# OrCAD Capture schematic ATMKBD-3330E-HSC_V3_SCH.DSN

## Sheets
1 1. TITLE: title: ATM3330e PV Keyboard Reference Design; rev: 3; note: <078-30-611-xxxx>
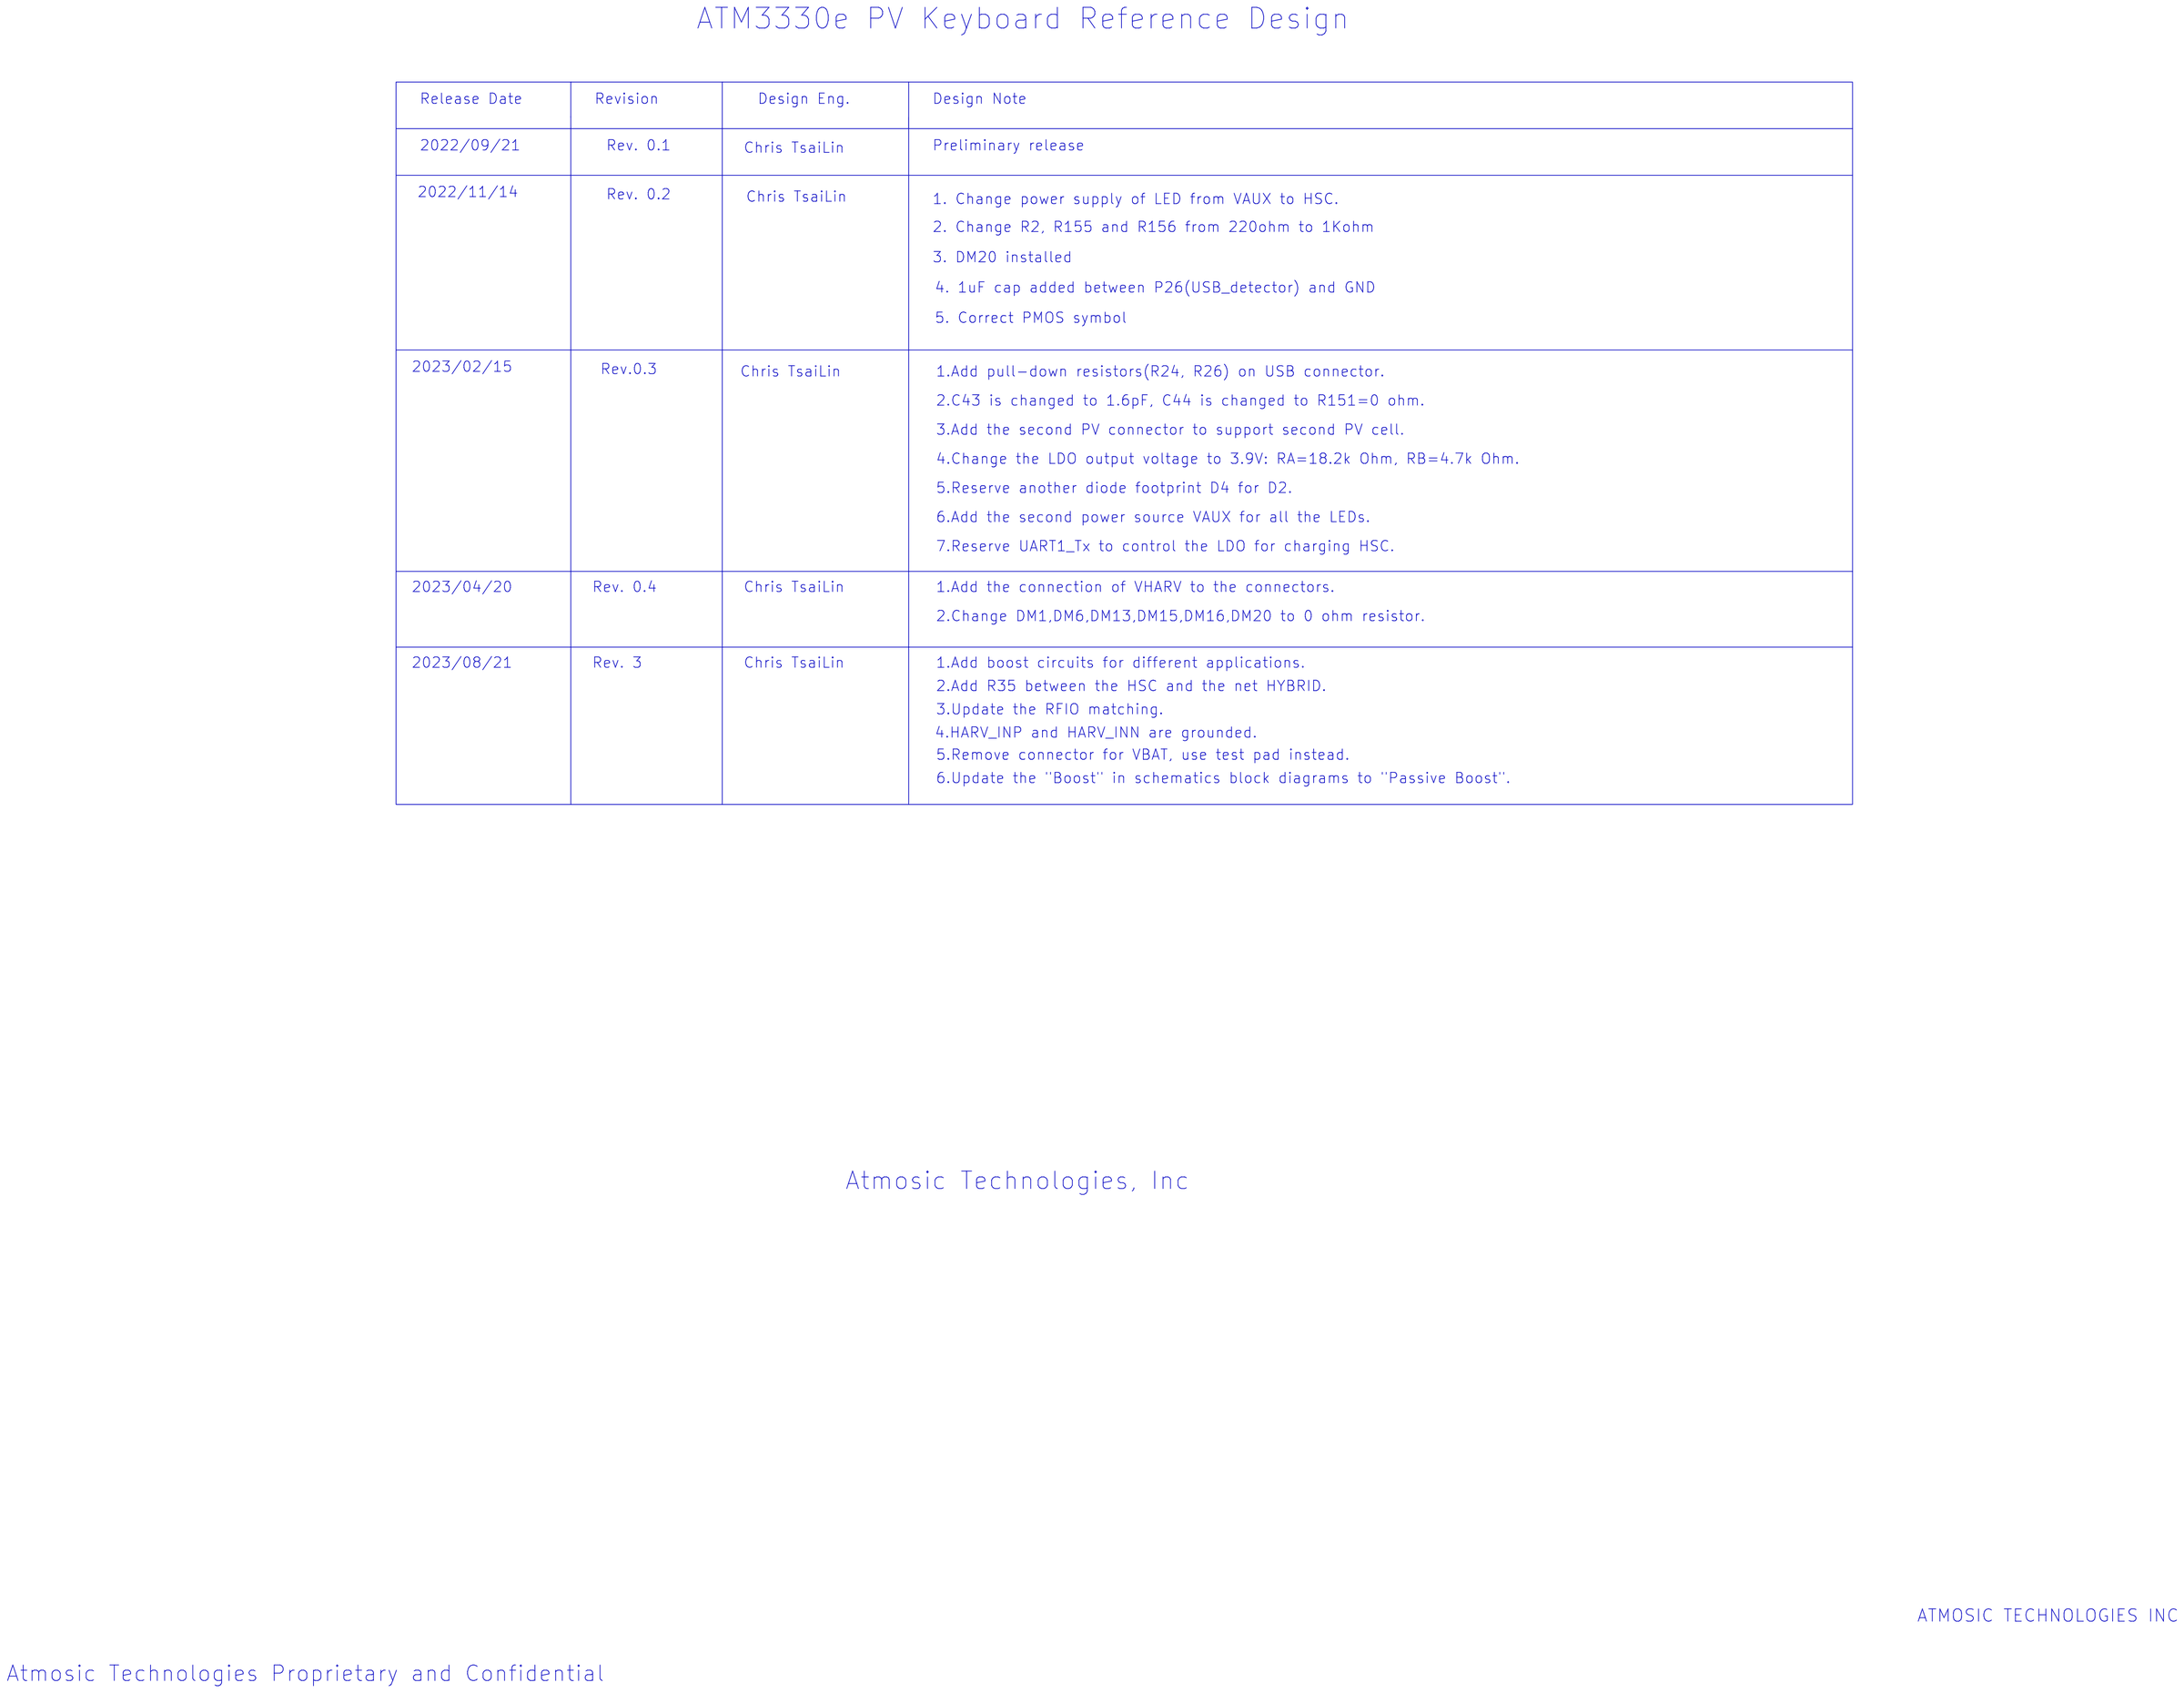
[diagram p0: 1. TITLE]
2 2. BLOCK DIAGRAM_1
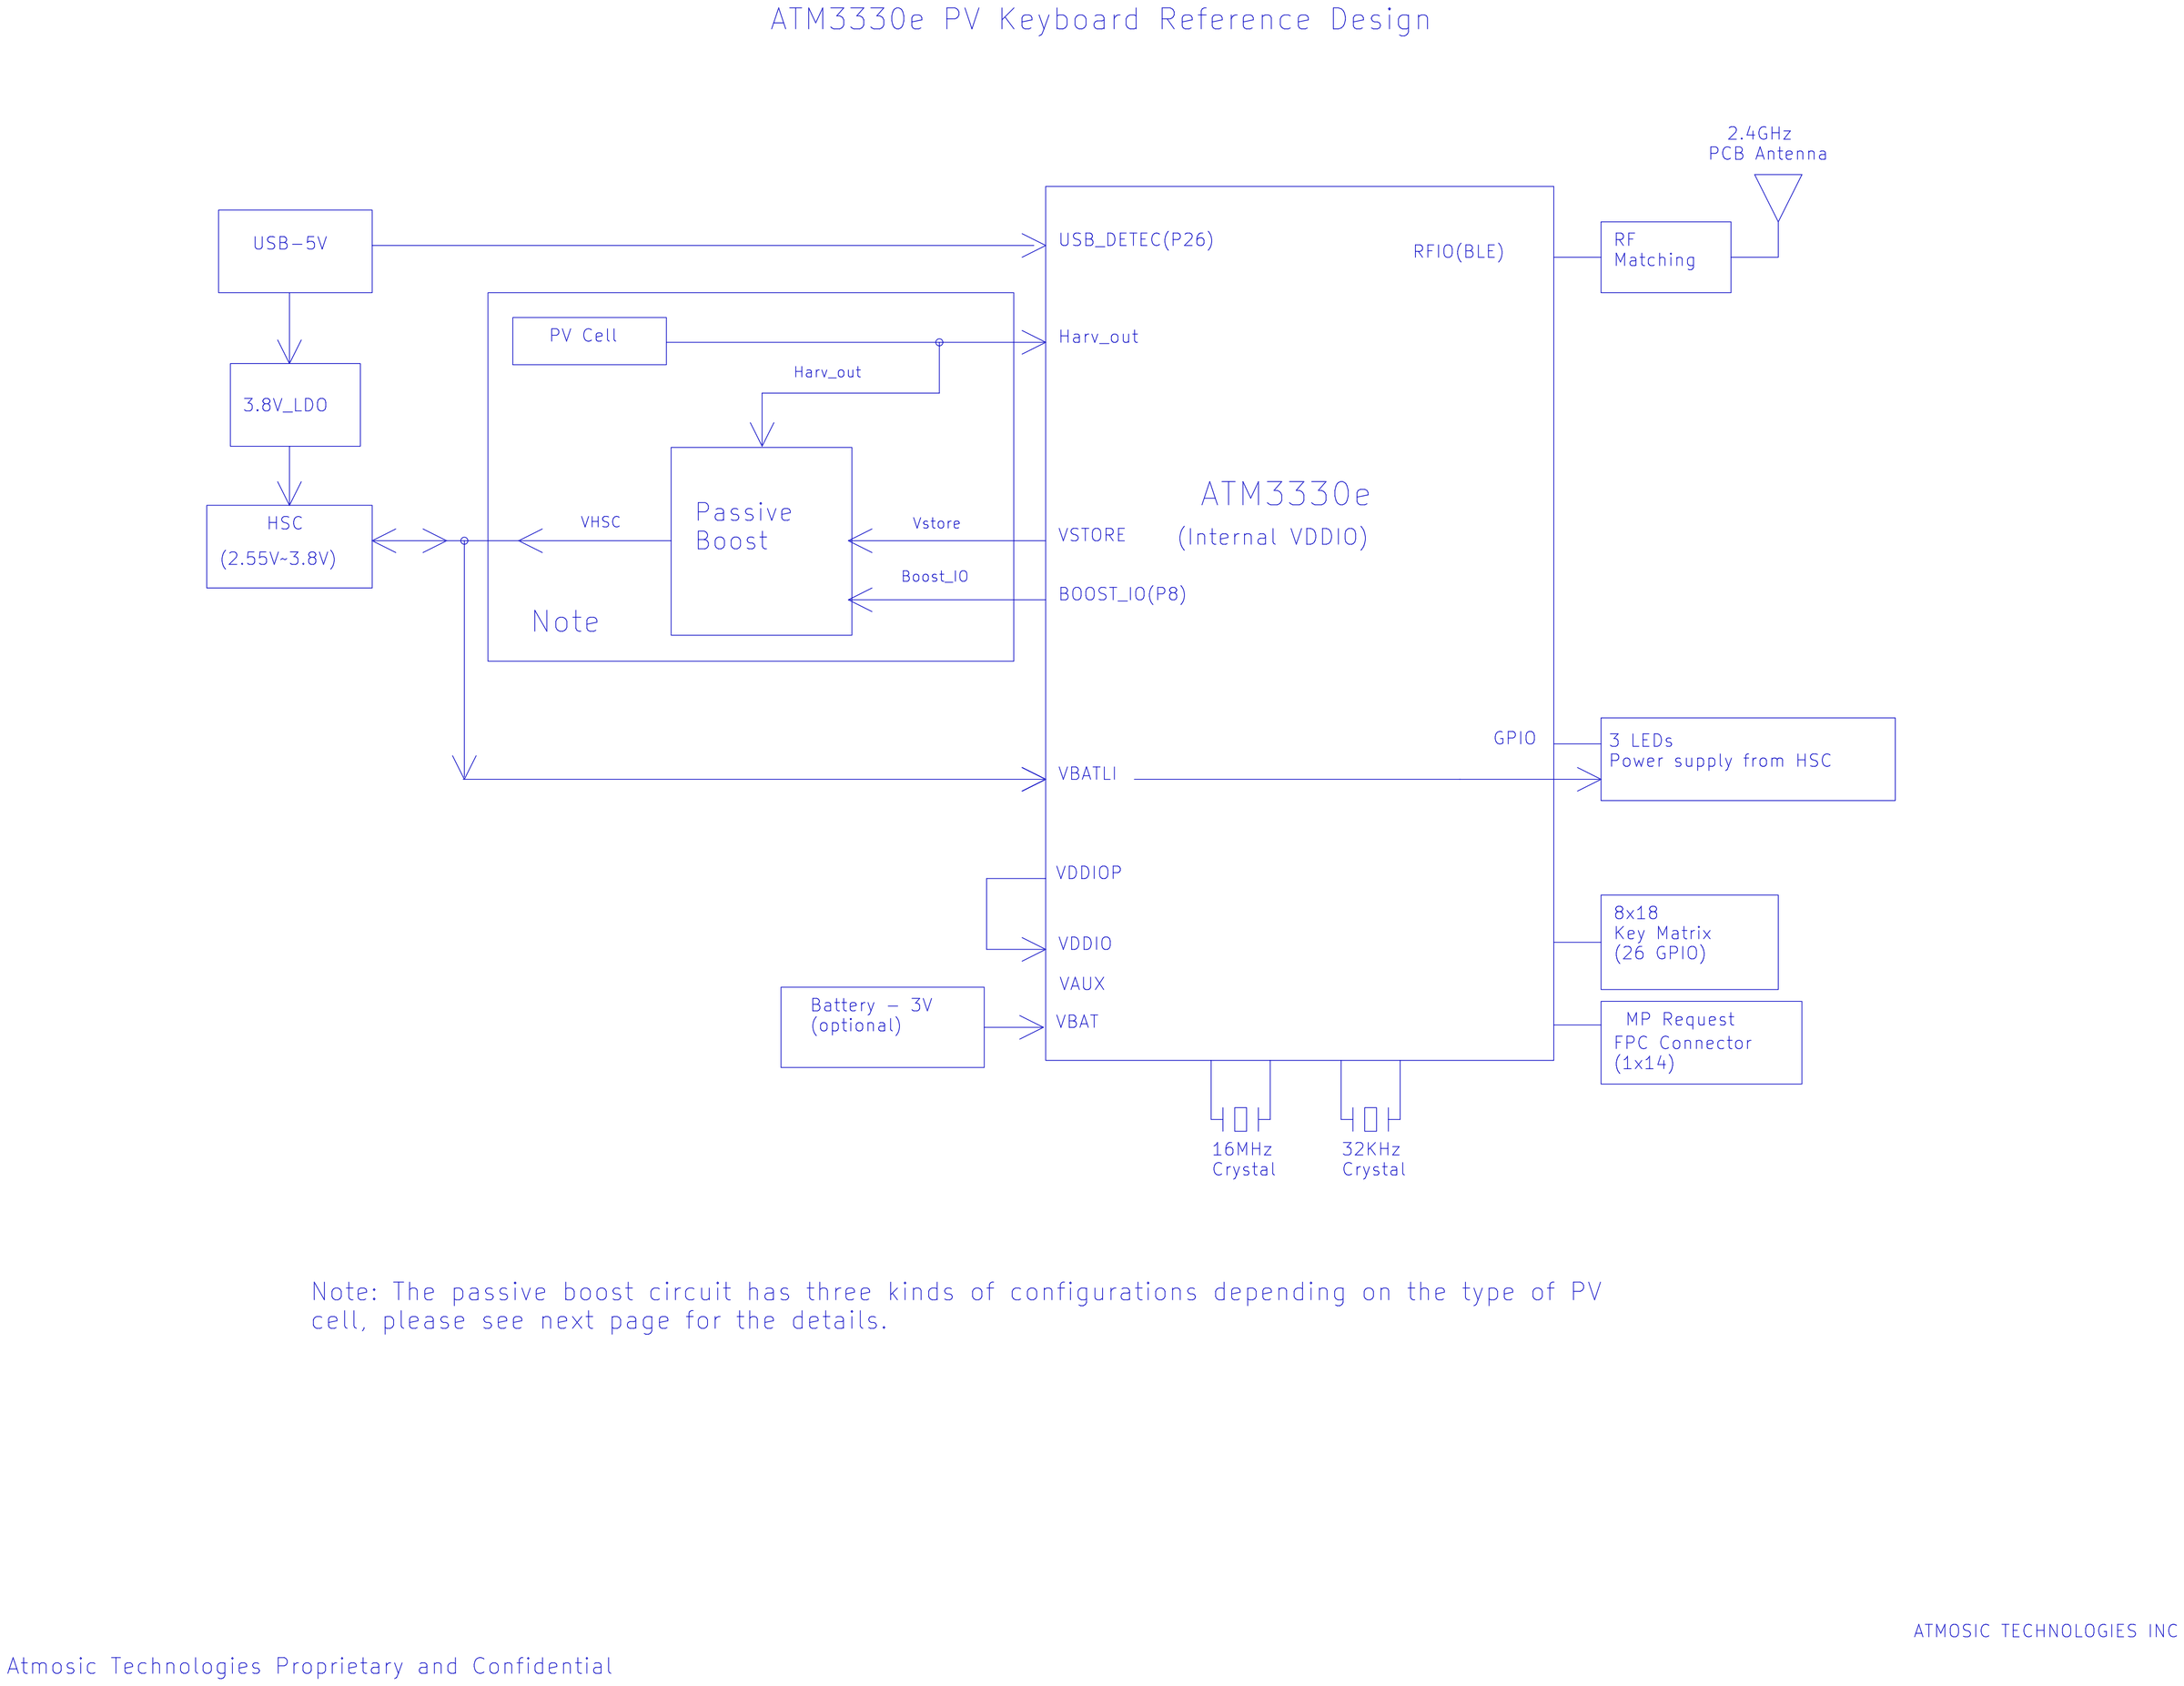
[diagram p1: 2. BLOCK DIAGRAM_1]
3 3. BLOCK DIAGRAM_2
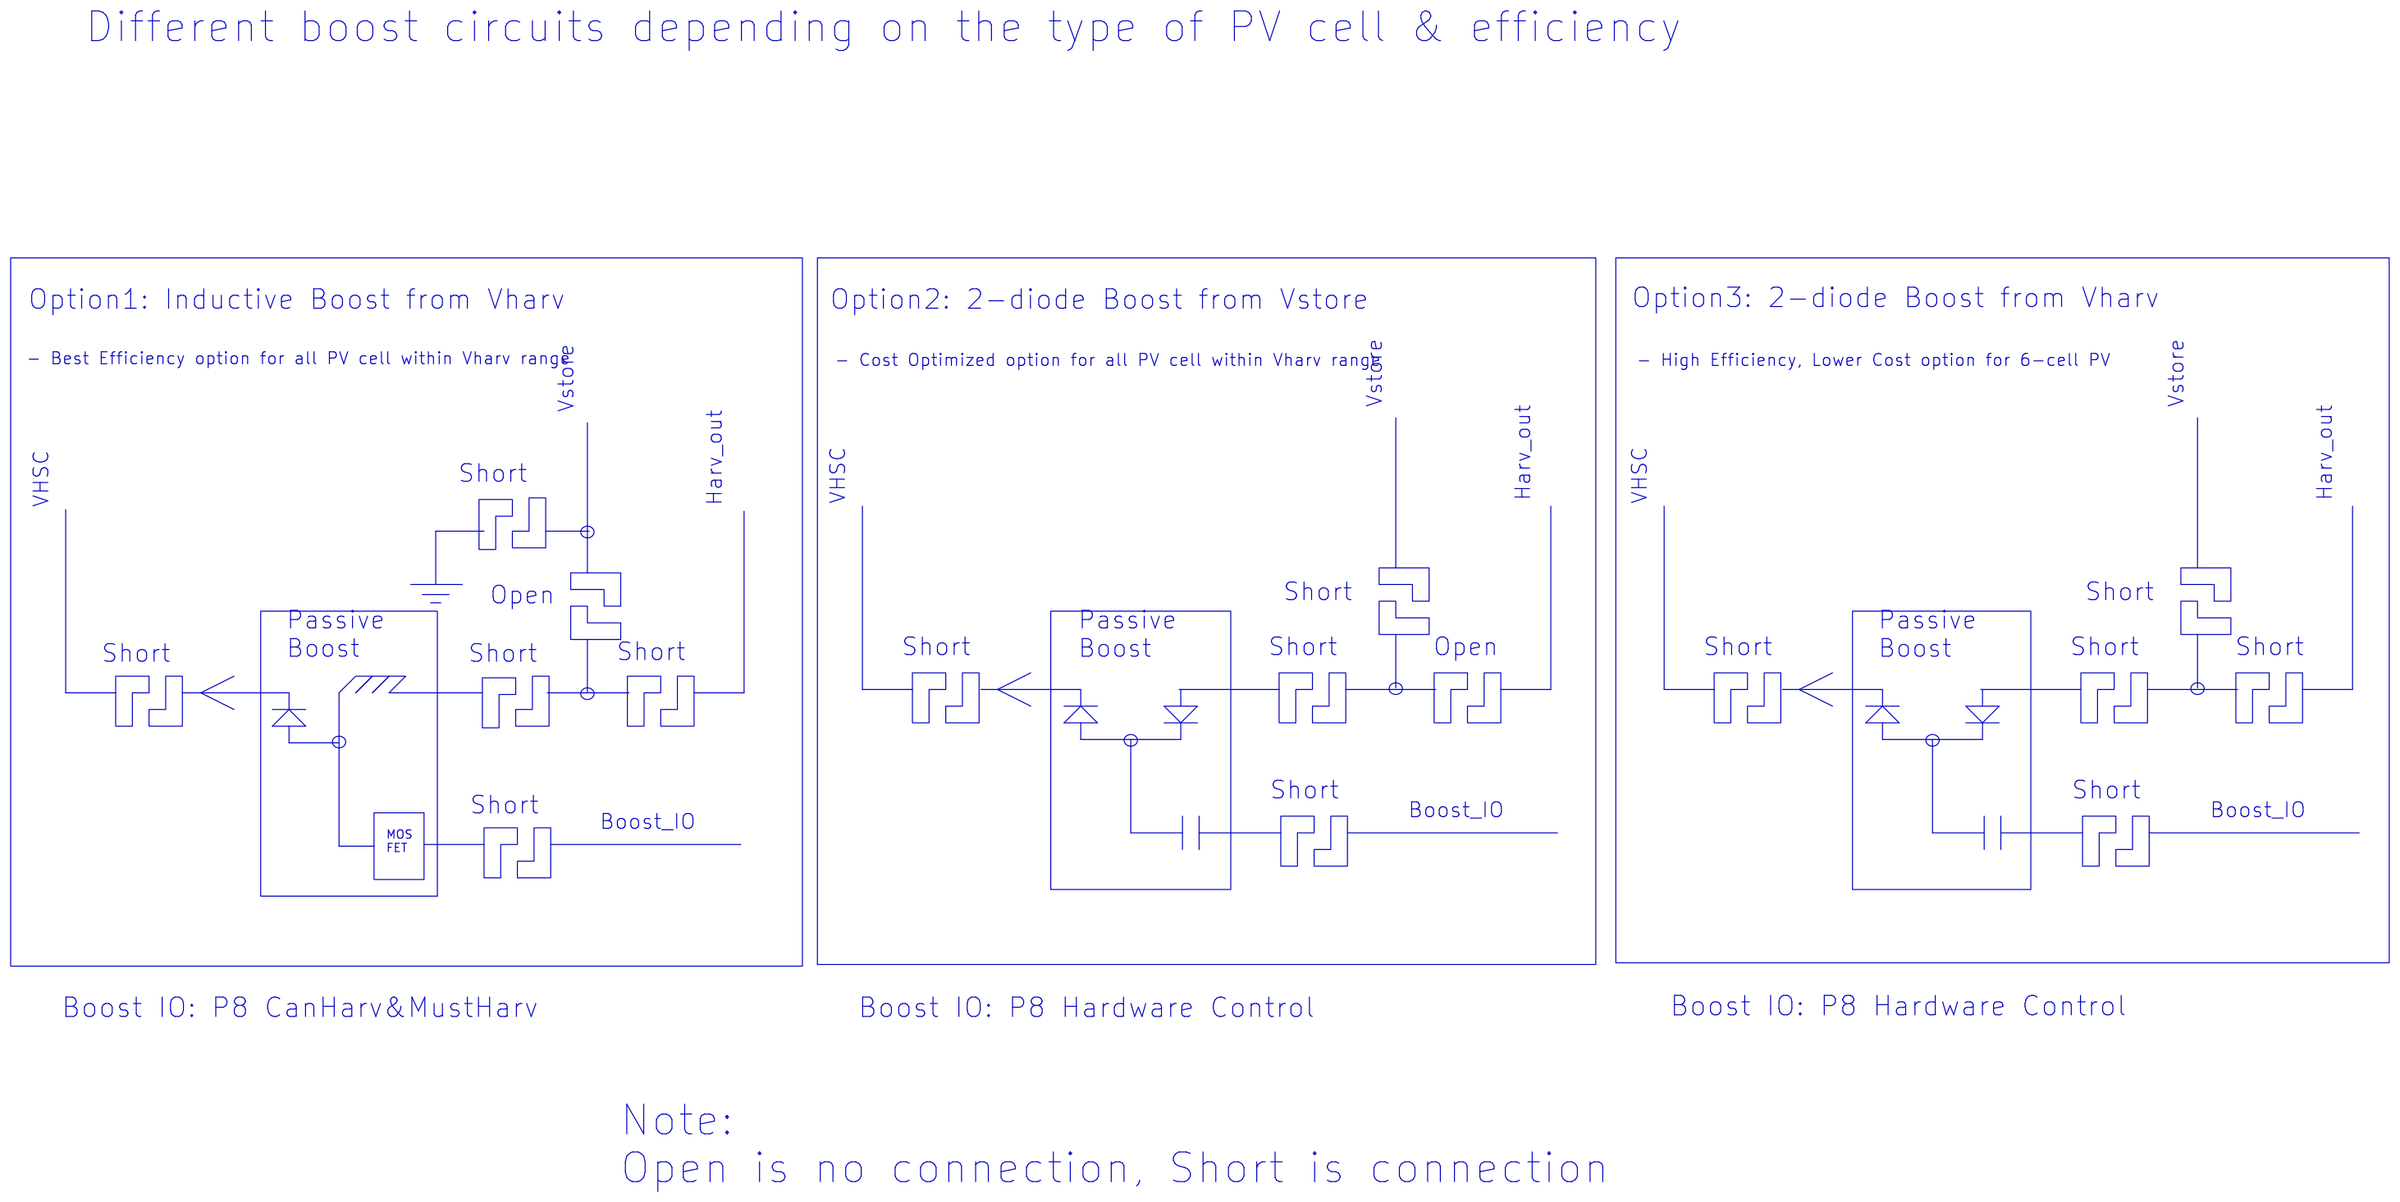
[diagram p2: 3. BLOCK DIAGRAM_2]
4 4. ATM3330e: size C
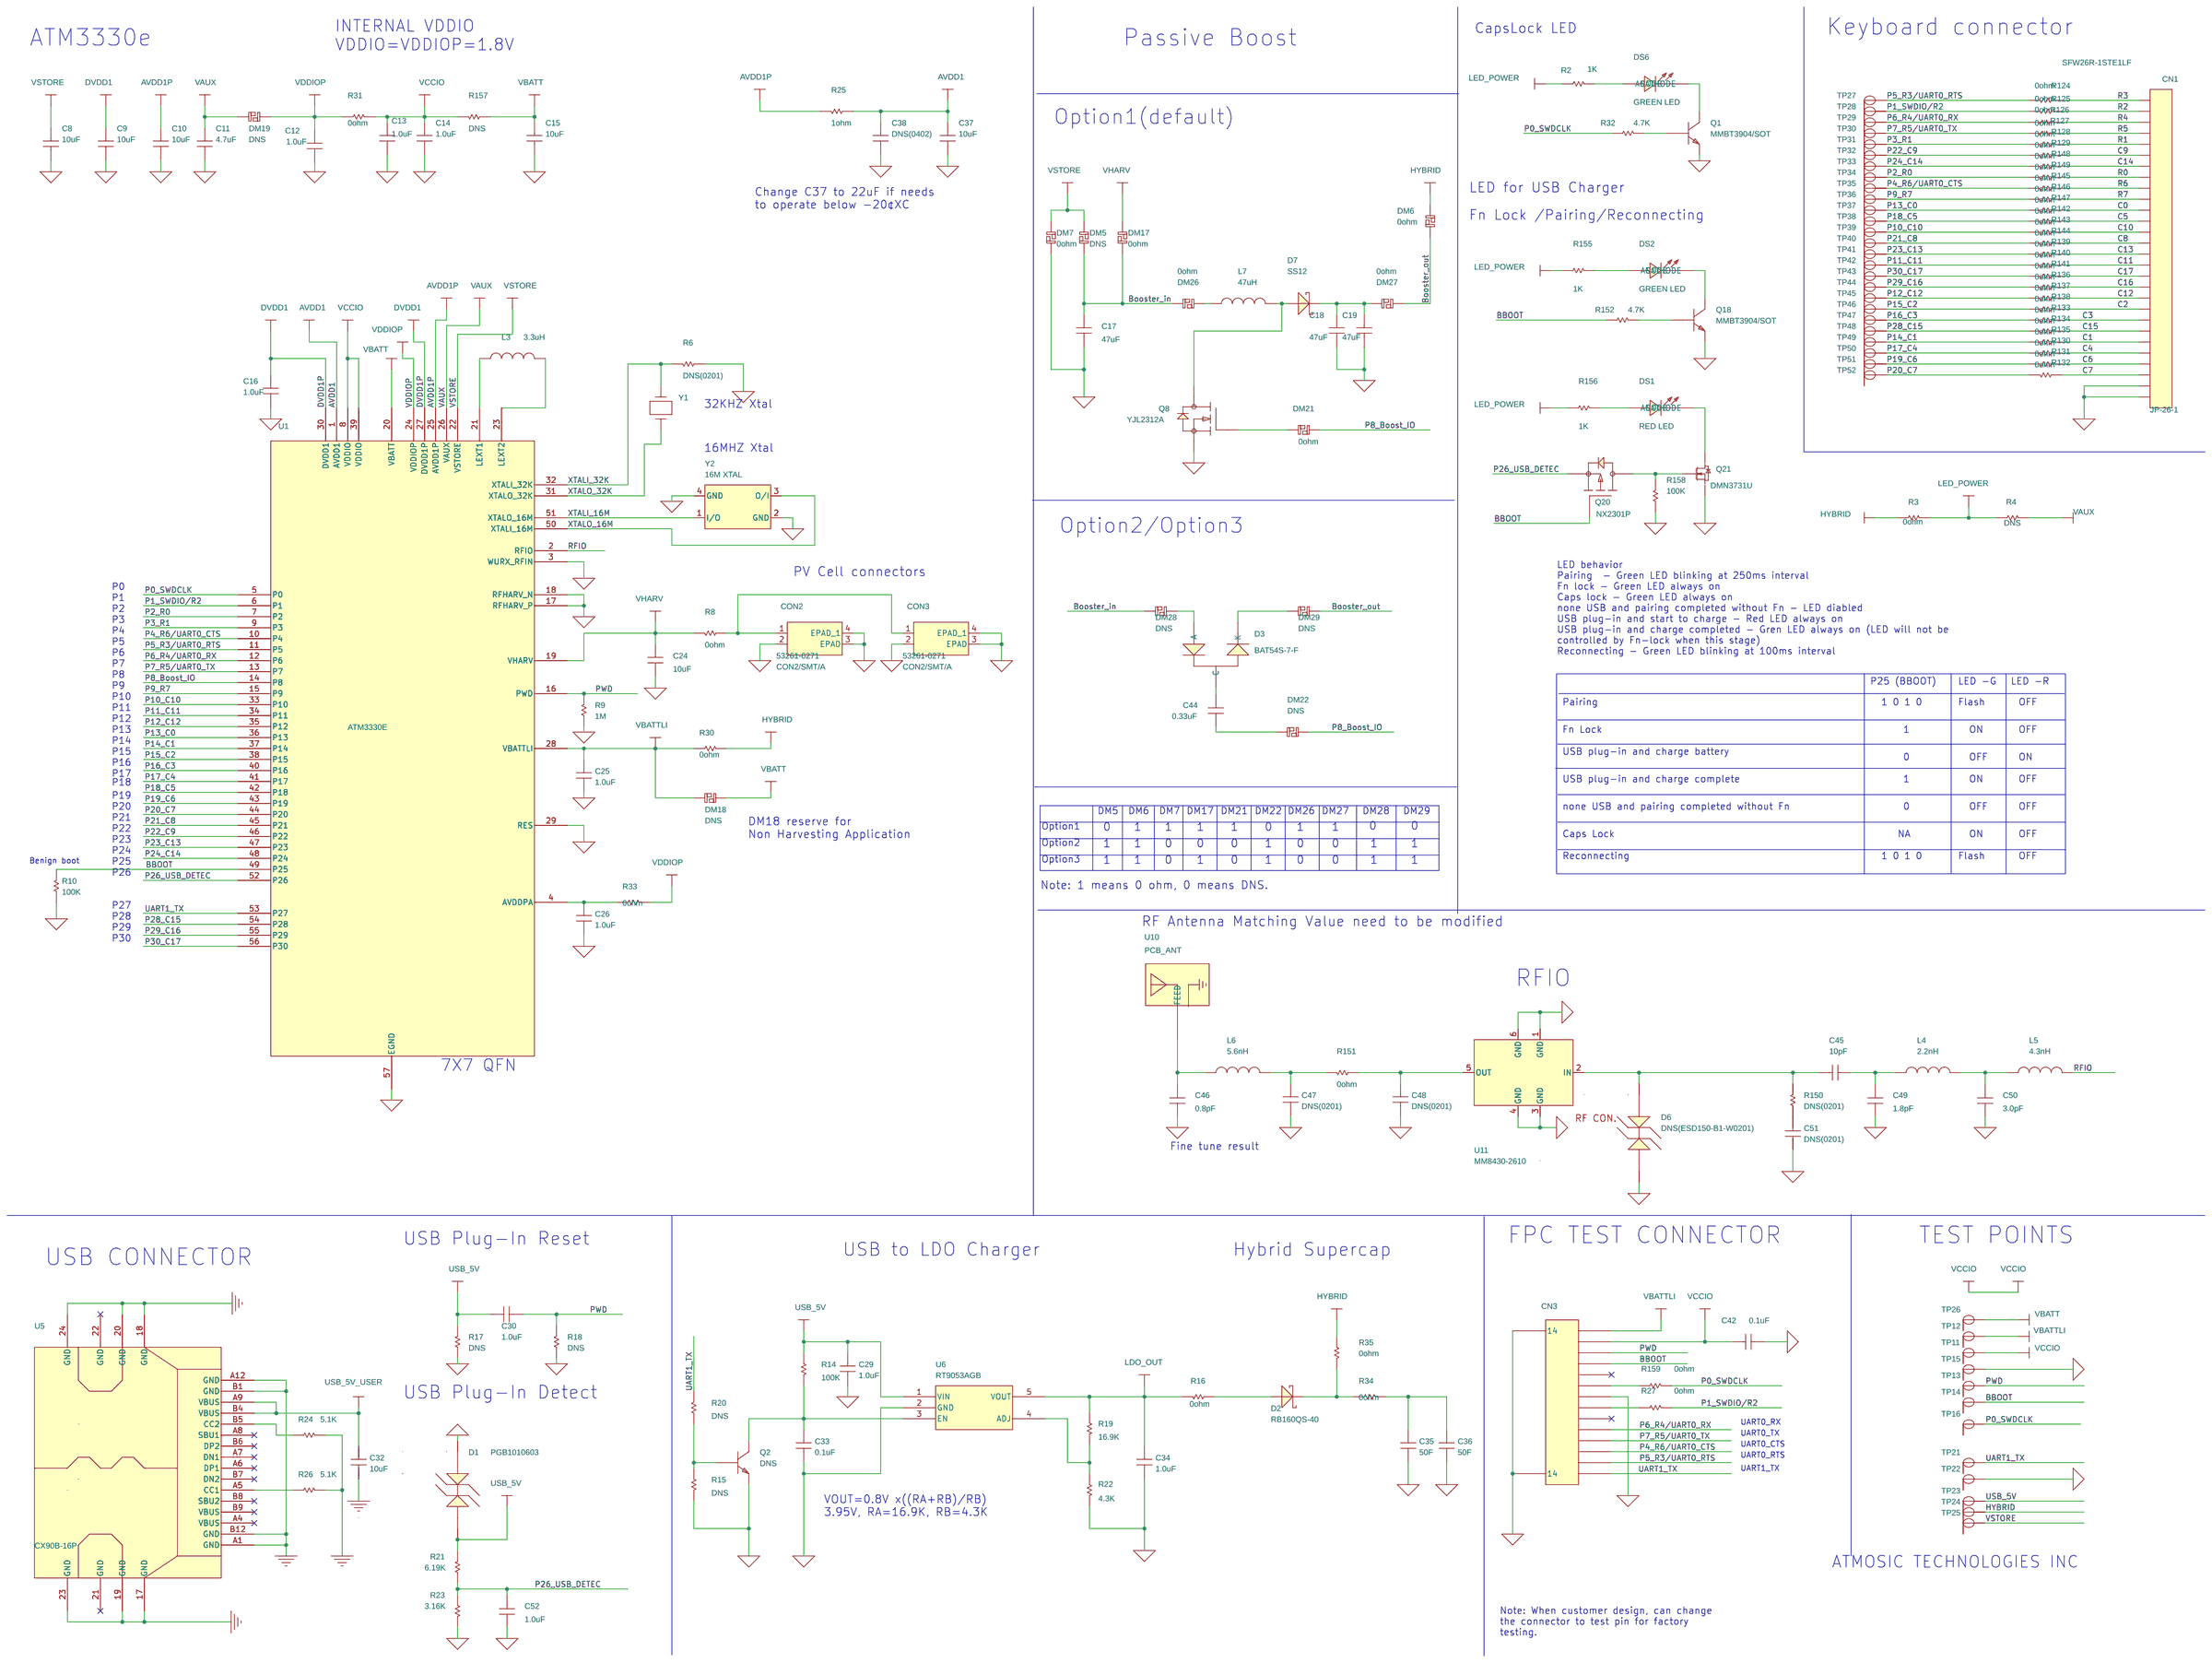
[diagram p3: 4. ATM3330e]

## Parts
C8  10uF  [0402]
C9  10uF  [0402]
C10  10uF  [0402]
C11  4.7uF  [0402]
C12  1.0uF  [0402]
C13  1.0uF  [0402]
C14  1.0uF  [0402]
C15  10uF  [0402]
C16  1.0uF  [0402]
C17  47uF  [1206]
C18  47uF  [1206]
C19  47uF  [1206]
C24  10uF  [0402]
C25  1.0uF  [0402]
C26  1.0uF  [0402]
C29  1.0uF  [0402]
C30  1.0uF  [0402]
C32  10uF  [0402]
C33  0.1uF  [0402]
C34  1.0uF  [0402]
C35  50F  [C_VEL08253R8506G]
C36  50F  [C_VEL08253R8506G]
C37  10uF  [0603]
C38  DNS(0402)  [0402]
C42  0.1uF  [0402]
C44  0.33uF  [0402]
C45  10pF  [0201]
C46  0.8pF  [0201]
C47  DNS(0201)  [0201]
C48  DNS(0201)  [0201]
C49  1.8pF  [0201]
C50  3.0pF  [0201]
C51  DNS(0201)  [0201]
C52  1.0uF  [0402]
CN1  SFW26R-1STE1LF  [JP-26-1]
CN3  05002HR-14CE  [FFC/0.5mm/14PIN]
CON2  53261-0271  [CON2/SMT/A]
CON3  53261-0271  [CON2/SMT/A]
D1  PGB1010603  [PGB1010603]
D2  RB160QS-40  [SMD1006]
D3  BAT54S-7-F  [SOT23]
D6  DNS(ESD150-B1-W0201)  [0201]
D7  SS12  [SMA_W]
DM5  DNS  [0402-DUMMY]
DM6  0ohm  [0402-DUMMY]
DM7  0ohm  [0402-DUMMY]
DM17  0ohm  [0402-DUMMY]
DM18  DNS  [0402-DUMMY]
DM19  DNS  [0402-DUMMY]
DM21  0ohm  [0402-DUMMY]
DM22  DNS  [0402-DUMMY]
DM26  0ohm  [0402-DUMMY]
DM27  0ohm  [0402-DUMMY]
DM28  DNS  [0402-DUMMY]
DM29  DNS  [0402-DUMMY]
DS1  RED LED  [LC-1206_LED_FT]
DS2  GREEN LED  [LC-1206_LED_FT]
DS6  GREEN LED  [LC-1206_LED_FT]
L3  3.3uH  [IND-2016-2]
L4  2.2nH  [0201]
L5  4.3nH  [0201]
L6  5.6nH  [0201]
L7  47uH  [L_MPIT6028]
Q1  MMBT3904/SOT  [TRA-SOT23]
Q2  DNS  [TRA-SOT23]
Q8  YJL2312A  [SOT23]
Q18  MMBT3904/SOT  [TRA-SOT23]
Q20  NX2301P  [TRA-SOT23]
Q21  DMN3731U  [TRA-SOT23]
R2  1K  [0402]
R3  0ohm  [0402]
R4  DNS  [0402]
R6  DNS(0201)  [0201]
R8  0ohm  [0402]
R9  1M  [0402]
R10  100K  [0402]
R14  100K  [0402]
R15  DNS  [0402]
R16  0ohm  [1206]
R17  DNS  [0402]
R18  DNS  [0402]
R19  16.9K  [0402]
R20  DNS  [0402]
R21  6.19K  [0201]
R22  4.3K  [0402]
R23  3.16K  [0201]
R24  5.1K  [0201]
R25  1ohm  [0402]
R26  5.1K  [0201]
R27  0ohm  [0201]
R30  0ohm  [0402]
R31  0ohm  [0402]
R32  4.7K  [0402]
R33  0ohm  [0402]
R34  0ohm  [0402]
R35  0ohm  [0402]
R124  0ohm  [0402]
R125  0ohm  [0402]
R126  0ohm  [0402]
R127  0ohm  [0402]
R128  0ohm  [0402]
R129  0ohm  [0402]
R130  0ohm  [0402]
R131  0ohm  [0402]
R132  0ohm  [0402]
R133  0ohm  [0402]
R134  0ohm  [0402]
R135  0ohm  [0402]
R136  0ohm  [0402]
R137  0ohm  [0402]
R138  0ohm  [0402]
R139  0ohm  [0402]
R140  0ohm  [0402]
R141  0ohm  [0402]
R142  0ohm  [0402]
R143  0ohm  [0402]
R144  0ohm  [0402]
R145  0ohm  [0402]
R146  0ohm  [0402]
R147  0ohm  [0402]
R148  0ohm  [0402]
R149  0ohm  [0402]
R150  DNS(0201)  [0201]
R151  0ohm  [0201]
R152  4.7K  [0402]
R155  1K  [0402]
R156  1K  [0402]
R157  DNS  [0402]
R158  100K  [0402]
R159  0ohm  [0201]
TP11  TP  [TP2]
TP12  TP  [TP2]
TP13  TP  [TP2]
TP14  TP  [TP2]
TP15  TP  [TP2]
TP16  TP  [TP2]
TP21  TP  [TP2]
TP22  TP  [TP2]
TP23  TP  [TP2]
TP24  TP  [TP2]
TP25  TP  [TP2]
TP26  TP  [TP2]
TP27  TP  [TP2]
TP28  TP  [TP2]
TP29  TP  [TP2]
TP30  TP  [TP2]
TP31  TP  [TP2]
TP32  TP  [TP2]
TP33  TP  [TP2]
TP34  TP  [TP2]
TP35  TP  [TP2]
TP36  TP  [TP2]
TP37  TP  [TP2]
TP38  TP  [TP2]
TP39  TP  [TP2]
TP40  TP  [TP2]
TP41  TP  [TP2]
TP42  TP  [TP2]
TP43  TP  [TP2]
TP44  TP  [TP2]
TP45  TP  [TP2]
TP46  TP  [TP2]
TP47  TP  [TP2]
TP48  TP  [TP2]
TP49  TP  [TP2]
TP50  TP  [TP2]
TP51  TP  [TP2]
TP52  TP  [TP2]
U1  ATM3330E  [QFN-56-7X7-0.4MM-EP5.2MM]
U5  CX90B-16P  [CX90B-16P-1]
U6  RT9053AGB  [SOT23-5]
U10  PCB_ANT  [ANTENNA_IIFA_4_R]
U11  MM8430-2610  [RF_SWD]
Y1  32K XTAL  [XTAL-SMD2-2.0X1.2MM]
Y2  16M XTAL  [XTAL-ECX-2236]

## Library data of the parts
C8-C10 C15 C24 C32 = SMALL_CAP: Manufacture_Name: MURATA; Manufacture_Part_Number: GRM155R60J106ME15D; Part Number: 01-2000011; Price: 0.006; Vendor: MURATA
C11 = SMALL_CAP: Manufacture_Name: TDK; Manufacture_Part_Number: CL05A475MO5NUNC; Part Number: 01-2000015; Price: 0.003; Vendor: TDK
C12-C14 C16 C25 C26 C29 C30 C34 C52 = SMALL_CAP: Manufacture_Name: MURATA; Manufacture_Part_Number: GRT155R61E105ME01D; Part Number: 01-2000007; Price: 0.003; Vendor: MURATA
C17 = SMALL_CAP: Manufacture_Name: SAMSUNG; Manufacture_Part_Number: CL31A476MQHNNNE; Part Number: 01-4000001; Price: 0.03; Vendor: MURATA
C18 C19 = SMALL_CAP: Manufacture_Name: SAMSUNG; Manufacture_Part_Number: CL31A476MQHNNNE; Part Number: 01-4000005; Price: 0.03; Vendor: MURATA
C33 C42 = SMALL_CAP: Manufacture_Name: MURATA; Manufacture_Part_Number: GMD155R71C104KA1D; Part Number: 01-2000002; Price: 0.0013; Vendor: MURATA
C35 C36 = SMALL_CAP: Manufacture_Name: VINATECH; Manufacture_Part_Number: VEL08253R8506G; Part Number: 01-4000002; Price: 0.54; Vendor: EATON
C37 = SMALL_CAP: Manufacture_Name: MURATA; Manufacture_Part_Number: GRM185R60J106ME15J; Part Number: 01-3000002; Price: 0.013; Vendor: MURATA
C38 = SMALL_CAP: Part Number: 01-2000016
C44 = SMALL_CAP: Manufacture_Name: SAMSUNG; Manufacture_Part_Number: CL05A334MQ5NNNC; Part Number: 01-2000004; Price: 0.003; Vendor: WALSIN
C45 = SMALL_CAP: Manufacture_Name: MURATA; Manufacture_Part_Number: GRM0335C1H100GA01D; Part Description: CAP CER 10PF +/- 2.0pF 50V C0G/NP0 0201; Part Number: 01-1000046; Price: 0.0019; Vendor: YAGEO
C46 = SMALL_CAP: Manufacture_Name: MURATA; Manufacture_Part_Number: GRM0335C1HR80WA01D; Part Description: CAP CER 0.8PF +/- 0.05pF 50V C0G/NP0 0201; Part Number: 01-1000011
C47 C48 C51 = SMALL_CAP: Part Number: 01-1000002
C49 = SMALL_CAP: Manufacture_Name: MURATA; Manufacture_Part_Number: GRM0335C1H1R8BA01D; Part Description: CAP CER 1.8PF +/- 0.1pF 50V C0G/NP0 0201; Part Number: 01-1000021; Price: 0.0019; Vendor: YAGEO
C50 = SMALL_CAP: Manufacture_Name: MURATA; Manufacture_Part_Number: GRM0335C1H3R0BA01D; Part Description: CAP CER 3.0PF +/- 0.1pF 50V C0G/NP0 0201; Part Number: 01-1000033; Price: 0.0019; Vendor: Murata
CN1 = CON4_17: Manufacture_Name: Amphenol ICC (FCI); Part Description: CONN FFC FPC BOTTOM 26POS 1MM RA; Part Number: 07-0000025; Price: 0.57; Vendor: Amphenol ICC (FCI)
CN3 = FFC_14PIN_0.5MM_D: Manufacture_Name: MOLEX; Manufacture_Part_Number: 503480-1400; Part Number: 07-0000001; Price: 0.3; Vendor: MOLEX
CON2 CON3 = CON4_2: Manufacture_Name: MOLEX; Part Description: CONN HEADER SMD R/A 2POS 1.25MM; Part Number: 07-0000026; Price: 0.224; Vendor: Molex
D1 = ESDP: Manufacture_Name: LITTELFUSE; Part Number: 06-0000061; Price: 0.05; Vendor: LITTELFUSE
D2 = TMP_3: Manufacture_Name: ROHM; Part Number: 06-0000012; Price: 0.08; Vendor: ROHM
D3 = DIODE_1A2C3COM: Manufacture_Name: DIODES; Manufacture_Part_Number: BAT54CT-7-F; Part Number: 06-0000001; Price: 0.013; Vendor: DIODES
D6 = ESDP: Manufacture_Name: INFINEON; Manufacture_Part_Number: ESD150-B1-W0201; Part Number: 06-0000002; Vendor: INFINEON
D7 = TMP_2: Manufacture_Name: Yangzhou Yangjie Electronic; Part Description: Schotty Rectifier Diode; Part Number: 06-0000063; Price: 0.012; Vendor: ROHM
DM5 DM6 DM22 = DUMMY: Manufacture_Name: PANASONIC; Manufacture_Part_Number: ERJ-2GE0R00X; Part Number: 03-2000017; Price: 0.0002; Vendor: WALSIN
DM7 DM17 DM19 DM21 DM26-DM29 = DUMMY: Part Number: 03-2000041; Vendor: WALSIN
DM18 = DUMMY: Part Number: 03-2000041
DS1 = LED_0: Part Number: 06-0000072
DS2 DS6 = LED_0: Part Number: 06-0000071
L3 = INDUCTOR: Manufacture_Name: MURATA; Manufacture_Part_Number: LQM2MPN3R3NG0L; Part Number: 02-4000002; Price: 0.04; Vendor: MURATA
L4 = INDUCTOR: Manufacture_Name: TDK; Manufacture_Part_Number: MHQ0603P2N2BT000; Part Number: 02-1000007; Vendor: TDK
L5 = INDUCTOR: Manufacture_Name: TDK; Manufacture_Part_Number: MHQ0603P4N3HT000; Part Number: 02-1000008; Vendor: TDK
L6 = INDUCTOR: Manufacture_Name: TDK; Manufacture_Part_Number: MHQ0603P5N6HT000; Part Number: 02-1000009; Vendor: TDK
L7 = INDUCTOR: Manufacture_Name: MICROGATE; Manufacture_Part_Number: MPIT5020-470M-LF; Part Number: 02-4000011; Price: 0.0195; Vendor: MURATA
Q1 Q2 Q18 = MMBT3904_SOT: Manufacture_Name: NEXPERIA; Manufacture_Part_Number: PMBT3904-215; Part Number: 06-0000022; Vendor: Micro Commercial Co
Q8 = MPF990_0: Manufacture_Name: Yangzhou Yangjie Electronic; Part Description: MOSFET N-CH 20V 6.8MA SOT-23; Part Number: 06-0000066; Price: 0.025; Vendor: ALPHA&OMEGA
Q20 = PWRMOSFET_EP_GSD_0: Manufacture_Name: NEXPERIA; Manufacture_Part_Number: NX2301P,215; Part Number: 06-0000026; Vendor: Nexperia
Q21 = MMBT3904_SOT_12: Manufacture_Name: DIODES; Part Description: MOSFET N-CH 30V 900MA SOT23; Part Number: 06-0000070; Price: 0.032; Vendor: DIODE
R2 R155 R156 = SMALL_R1: Manufacture_Name: WALSIN; Manufacture_Part_Number: WR04X1001FTL; Part Description: RES 1K OHM 1% 0402; Part Number: 03-2000028; Price: 0.0002; Vendor: WALSIN
R3 R8 R124-R149 = SMALL_R1: Manufacture_Name: PANASONIC; Manufacture_Part_Number: ERJ-2GE0R00X; Part Number: 03-2000018; Price: 0.0002; Vendor: WALSIN
R4 R15 R20 = SMALL_R1: Part Number: 03-2000042; Vendor: WALSIN
R6 R150 = SMALL_R1: Part Number: 03-1000003
R9 = SMALL_R1: Manufacture_Name: WALSIN; Manufacture_Part_Number: WR04X1004FTL; Part Number: 03-2000029; Price: 0.0002; Vendor: WALSIN
R10 R14 R158 = SMALL_R1: Manufacture_Name: WALSIN; Manufacture_Part_Number: WR04X1003FTL; Part Number: 03-2000019; Price: 0.0002; Vendor: WALSIN
R16 = SMALL_R1: Manufacture_Name: WALSIN; Manufacture_Part_Number: WR12X000 PTL; Part Number: 03-4000003; Price: 0.0008; Vendor: WALSIN
R17 R18 R157 = SMALL_R1: Part Number: 03-2000042
R19 = SMALL_R1: Manufacture_Name: YAGEO; Manufacture_Part_Number: RC0402FR-0716K9L; Part Description: RES 16.9K OHM 1% 0402; Part Number: 03-2000075; Price: 0.0002; Vendor: WALSIN
R21 = SMALL_R1: Manufacture_Name: YAGEO; Manufacture_Part_Number: RC0201FR-076K19L; Part Description: RES 6.19K OHM 1% 1/20W 0201; Part Number: 03-1000022; Price: 0.0005
R22 = SMALL_R1: Manufacture_Name: YAGEO; Manufacture_Part_Number: RC0402FR-074K3L; Part Description: RES 4.3K OHM 1% 0402; Part Number: 03-2000074; Price: 0.0002; Vendor: WALSIN
R23 = SMALL_R1: Manufacture_Name: YAGEO; Manufacture_Part_Number: RC0201FR-073K16L; Part Description: RES 3.16K OHM 1% 1/20W 0201; Part Number: 03-1000021; Price: 0.0005
R24 R26 = SMALL_R1: Manufacture_Name: YAGEO; Manufacture_Part_Number: AC0201FR-075K1L; Part Description: RES SMD 5.1K OHM 1% 1/20W 0201; Part Number: 03-1000015; Price: 0.0005
R25 = SMALL_R1: Manufacture_Name: YAGEO; Manufacture_Part_Number: RC0402FR-071RL; Part Description: RES 1 OHM 1% 1/16W 0402; Part Number: 03-2000032; Price: 0.0002; Vendor: YAGEO
R27 R159 = SMALL_R1: Manufacture_Name: YAGEO; Manufacture_Part_Number: AC0201JR-070RL; Part Description: 0,L-0201-H0_33,Cyntec; Part Number: 03-1000002; Price: 0.0005; Vendor: WALSIN
R30 R31 R33-R35 = SMALL_R1: Manufacture_Name: PANASONIC; Manufacture_Part_Number: ERJ-2GE0R00X; Part Number: 03-2000018; Price: 0.0002; Vendor: YAGEO
R32 R152 = SMALL_R1: Manufacture_Name: WALSIN; Manufacture_Part_Number: WR04X4701FTL; Part Number: 03-2000038; Price: 0.0002; Vendor: WALSIN
R151 = SMALL_R1: Manufacture_Name: YAGEO; Manufacture_Part_Number: AC0201JR-070RL; Part Description: RES SMD 0 OHM 1% 1/20W 0201; Part Number: 03-1000007; Price: 0.0005
TP11-TP16 TP21-TP52 = TP_0: Part Number: 09-0000001
U1 = ATM3332-202_0: Manufacture_Name: Atmosic; Manufacture_Part_Number: ATM3330e; Part Number: 04-0000003; Vendor: ATMOSIC
U5 = USB_Connector_TypeC_5: Manufacture_Name: HIROSE; Part Number: 07-0000003; Price: 0.14; Vendor: HIROSE
U6 = LDO_RT9179PB: Manufacture_Name: RICHTEK; Part Number: 06-0000004; Price: 0.065; Vendor: RICHTEK
U10 = ANT-FEED-GND_0: PCB, Antenna For BCM920707EMB; Assembly Instructions: DO NOT INSTALL; BRCMPN: OPEN; Buy Instructions: DO NOT BUY; Critical: Y; Description 2: No_Physical_Part; Device File: ANTENNA-124865-0000_01; Part Number: 09-0000010; Vendor: NA; Vendor PN: NA
U11 = RF_SWJ_7: Manufacture_Name: MURATA; Part Number: 07-0000002; Price: 0.12; Vendor: MURATA
Y1 = XTAL: Manufacture_Name: SEIKO; Manufacture_Part_Number: SC20S-7PF20PPM; Part Number: 06-0000018; Price: 0.1; Vendor: SEIKO
Y2 = XTAL-OSC-4P_3: Manufacture_Name: ECS; Manufacture_Part_Number: ECS-160-8-36-JTN-TR; Part Number: 06-0000013; Price: 0.1; Vendor: ECS

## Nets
AVDD1: C37.1 C38.1 R25.1 U1.1(AVDD1)
AVDD1P: C10.1 R25.2 U1.25(AVDD1P)
DVDD1: C9.1 C16.1 U1.27(DVDD1P) U1.30(DVDD1)
GND_POWER: C32.2 R24.1 R26.1 U5.17(GND) U5.18(GND) U5.19(GND) U5.20(GND) U5.23(GND) U5.24(GND) U5.A1(GND) U5.A12(GND) U5.B1(GND) U5.B12(GND)
GND_SIGNAL: C8.2 C9.2 C10.2 C11.2 C12.2 C13.2 C14.2 C15.2 C16.2 C17.2 C18.2 C19.2 C24.2 C25.2 C26.2 C29.2 C33.2 C34.2 C35.2 C36.2 C37.2 C38.2 C42.2 C46.1 C47.2 C48.2 C49.1 C50.1 C51.1 C52.1 CN1.27 CN1.28 CN3.7 CN3.15(14) CN3.16(14) CON2.2 CON2.3(EPAD) CON2.4(EPAD_1) CON3.2 CON3.3(EPAD) CON3.4(EPAD_1) D1.2 D6.1 DM7.2 Q1.2(E) Q2.2(E) Q8.2(SOURCE) Q18.2(E) Q21.2(S) R6.1 R9.1 R10.1 R15.1 R17.1 R18.1 R22.1 R23.1 R158.1 TP15.1(TP) TP22.1(TP) U1.3(WURX_RFIN) U1.17(RFHARV_P) U1.18(RFHARV_N) U1.29(RES) U1.57(EGND) U6.2(GND) U11.1(GND) U11.3(GND) U11.4(GND) U11.6(GND) Y2.2(GND) Y2.4(GND)
VBATT: C15.1 DM18.2 R157.1 TP26.1(TP) U1.20(VBATT)
VBATTLI: C25.1 CN3.1 DM18.1 R30.1 TP12.1(TP) U1.28(VBATTLI)
VCCIO: C13.1 C14.1 C42.1 CN3.2 R31.2 R157.2 TP11.1(TP) U1.8(VDDIO) U1.39(VDDIO)
VDDIOP: C12.1 DM19.2 R31.1 R33.2 U1.24(VDDIOP)
BBOOT: CN3.4 Q20.1(GATE) R10.2 R152.1 TP14.1(TP) U1.49(P25)
Booster_in: C17.1 DM5.2 DM17.2 DM26.1 DM28.1
Booster_out: DM6.2 DM27.2 DM29.2
C0: CN1.11 R147.2
C1: CN1.23 R135.2
C2: CN1.20 R138.2
C3: CN1.21 R133.2
C4: CN1.24 R130.2
C5: CN1.12 R142.2
C6: CN1.25 R131.2
C7: CN1.26 R132.2
C8: CN1.14 R144.2
C9: CN1.6 R129.2
C10: CN1.13 R143.2
C11: CN1.16 R140.2
C12: CN1.19 R137.2
C13: CN1.15 R139.2
C14: CN1.7 R148.2
C15: CN1.22 R134.2
C16: CN1.18 R136.2
C17: CN1.17 R141.2
HYBRID: DM6.1 R3.2 R30.2 R35.1 TP24.1(TP)
LDO_OUT: C34.1 R16.2 R19.2 U6.5(VOUT)
LED_POWER: R2.2 R3.1 R4.2 R155.2 R156.2
P0_SWDCLK: R32.1 R159.2 TP16.1(TP) U1.5(P0)
P1_SWDIO/R2: R27.2 R125.1 TP28.1(TP) U1.6(P1)
P2_R0: R149.1 TP34.1(TP) U1.7(P2)
P3_R1: R128.1 TP31.1(TP) U1.9(P3)
P4_R6/UART0_CTS: CN3.12 R145.1 TP35.1(TP) U1.10(P4)
P5_R3/UART0_RTS: CN3.13 R124.1 TP27.1(TP) U1.11(P5)
P6_R4/UART0_RX: CN3.10 R126.1 TP29.1(TP) U1.12(P6)
P7_R5/UART0_TX: CN3.11 R127.1 TP30.1(TP) U1.13(P7)
P8_Boost_IO: DM21.2 DM22.2 U1.14(P8)
P9_R7: R146.1 TP36.1(TP) U1.15(P9)
P10_C10: R143.1 TP39.1(TP) U1.33(P10)
P11_C11: R140.1 TP42.1(TP) U1.34(P11)
P12_C12: R137.1 TP45.1(TP) U1.35(P12)
P13_C0: R147.1 TP37.1(TP) U1.36(P13)
P14_C1: R135.1 TP49.1(TP) U1.37(P14)
P15_C2: R138.1 TP46.1(TP) U1.38(P15)
P16_C3: R133.1 TP47.1(TP) U1.40(P16)
P17_C4: R130.1 TP50.1(TP) U1.41(P17)
P18_C5: R142.1 TP38.1(TP) U1.42(P18)
P19_C6: R131.1 TP51.1(TP) U1.43(P19)
P20_C7: R132.1 TP52.1(TP) U1.44(P20)
P21_C8: R144.1 TP40.1(TP) U1.45(P21)
P22_C9: R129.1 TP32.1(TP) U1.46(P22)
P23_C13: R139.1 TP41.1(TP) U1.47(P23)
P24_C14: R148.1 TP33.1(TP) U1.48(P24)
P26_USB_DETEC: C52.2 Q20.2(SOURCE) R21.2 R23.2 U1.52(P26)
P28_C15: R134.1 TP48.1(TP) U1.54(P28)
P29_C16: R136.1 TP44.1(TP) U1.55(P29)
P30_C17: R141.1 TP43.1(TP) U1.56(P30)
PWD: C30.2 CN3.3 R9.2 R18.2 TP13.1(TP) U1.16(PWD)
R0: CN1.8 R149.2
R1: CN1.5 R128.2
R2: CN1.2 R125.2
R3: CN1.1 R124.2
R4: CN1.3 R126.2
R5: CN1.4 R127.2
R6: CN1.9 R145.2
R7: CN1.10 R146.2
RFIO: L5.2 U1.2(RFIO)
UART1_TX: CN3.14 R20.1 TP21.1(TP) U1.53(P27)
USB_5V: C29.1 C30.1 D1.1 R14.2 R17.2 R21.1 TP23.1(TP) U6.1(VIN)
USB_5V_user: C32.1 U5.A9(VBUS) U5.B4(VBUS)
VAUX: C11.1 DM19.1 R4.1 U1.26(VAUX)
VHARV: C24.1 DM17.1 R8.2 U1.19(VHARV)
VSTORE: C8.1 DM5.1 DM7.1 TP25.1(TP) U1.22(VSTORE)
XTALI_16M: U1.51(XTALO_16M) Y2.1(I/O)
XTALI_32K: R6.2 U1.32(XTALI_32K) Y1.2
XTALO_16M: U1.50(XTALI_16M) Y2.3(O/I)
XTALO_32K: U1.31(XTALO_32K) Y1.1
N17310736: L3.1 U1.21(LEXT1)
N17310738: L3.2 U1.23(LEXT2)
N17310985: CON2.1 CON3.1 R8.1
N17334291: C33.1 Q2.3(C) R14.1 U6.3(EN)
N17334313: C35.1 C36.1 R34.2
N17334336: R19.1 R22.2 U6.4(ADJ)
N17375235: D2.2 R16.1
N17436807: C46.2 L6.1 U10.1(FEED)
N17436811: C47.1 L6.2 R151.2
N17436817: C48.1 R151.1 U11.5(OUT)
N17436821: C45.2 D6.2 R150.2 U11.2(IN)
N17436831: C45.1 C49.2 L4.1
N17436837: C50.2 L4.2 L5.1
N17461009: Q20.3(DRAIN) Q21.1(G) R158.2
N17490726: R24.2 U5.B5(CC2)
N17490775: R26.2 U5.A5(CC1)
N17494551: C26.1 R33.1 U1.4(AVDDPA)
N17508397: DS1.1(CATHODE) Q21.3(D)
N17509342: DS6.1(CATHODE) Q1.3(C)
N17509358: Q1.1(B) R32.2
N17509624: DS2.1(CATHODE) Q18.3(C)
N17509699: DS2.2(ANODE) R155.1
N17509751: Q18.1(B) R152.2
N17518441: DS6.2(ANODE) R2.1
N17519857: Q2.1(B) R15.2 R20.2
N17521073: D2.1 R34.1 R35.2
N17531340: C18.1 C19.1 D7.2 DM27.1
N17531506: DM21.1 Q8.1(GATE)
N17531508: D7.1 L7.2 Q8.3(DRAIN)
N17538313: CN3.6 R159.1
N17538315: CN3.8 R27.1
N17545463: C44.1 DM22.1
N17560015: D3.2(K) DM29.1
N17560027: D3.1(A) DM28.2
N17560037: C44.2 D3.3(C)
N17699214: DS1.2(ANODE) R156.1
N17724965: DM26.2 L7.1
N17740652: C51.2 R150.1

Not connected (* = marked no-connect by the designer): CN3 5* 9*; U5 21(GND)* 22(GND)* A4(VBUS)* A6(DP1)* A7(DN1)* A8(SBU1)* B6(DP2)* B7(DN2)* B8(SBU2)* B9(VBUS)*

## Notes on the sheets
sheet 1
- ATM3330e PV Keyboard Reference Design
- Release Date
- Revision
- Design Eng.
- Design Note
- 2022/09/21
- Rev. 0.1
- Chris TsaiLin
- Preliminary release
- 2022/11/14
- Rev. 0.2
- Chris TsaiLin
- 1. Change power supply of LED from VAUX to HSC.
- 2. Change R2, R155 and R156 from 220ohm to 1Kohm
- 3. DM20 installed
- 4. 1uF cap added between P26(USB_detector) and GND
- 5. Correct PMOS symbol
- 2023/02/15
- Rev.0.3
- Chris TsaiLin
- 1.Add pull-down resistors(R24, R26) on USB connector.
- 2.C43 is changed to 1.6pF, C44 is changed to R151=0 ohm.
- 3.Add the second PV connector to support second PV cell.
- 4.Change the LDO output voltage to 3.9V: RA=18.2k Ohm, RB=4.7k Ohm.
- 5.Reserve another diode footprint D4 for D2.
- 6.Add the second power source VAUX for all the LEDs.
- 7.Reserve UART1_Tx to control the LDO for charging HSC.
- 2023/04/20
- Rev. 0.4
- Chris TsaiLin
- 1.Add the connection of VHARV to the connectors.
- 2.Change DM1,DM6,DM13,DM15,DM16,DM20 to 0 ohm resistor.
- 2023/08/21
- Rev. 3
- Chris TsaiLin
- 1.Add boost circuits for different applications.
- 2.Add R35 between the HSC and the net HYBRID.
- 3.Update the RFIO matching.
- 4.HARV_INP and HARV_INN are grounded.
- 5.Remove connector for VBAT, use test pad instead.
- 6.Update the "Boost" in schematics block diagrams to "Passive Boost".
- Atmosic Technologies, Inc
- ATMOSIC TECHNOLOGIES INC
- Atmosic Technologies Proprietary and Confidential
sheet 2
- ATM3330e PV Keyboard Reference Design
- 2.4GHz
  PCB Antenna
- USB_DETEC(P26)
- RF
  Matching
- USB-5V
- RFIO(BLE)
- PV Cell
- Harv_out
- Harv_out
- 3.8V_LDO
- ATM3330e
- Passive
  Boost
- HSC
- VHSC
- Vstore
- VSTORE
- (Internal VDDIO)
- (2.55V~3.8V)
- Boost_IO
- BOOST_IO(P8)
- Note
- GPIO
- 3 LEDs
  Power supply from HSC
- VBATLI
- VDDIOP
- 8x18
  Key Matrix
  (26 GPIO)
- VDDIO
- VAUX
- Battery - 3V
  (optional)
- VBAT
- MP Request
- FPC Connector
  (1x14)
- 16MHz
  Crystal
- 32KHz
  Crystal
- Note: The passive boost circuit has three kinds of configurations depending on the type of PV
  cell, please see next page for the details.
- ATMOSIC TECHNOLOGIES INC
- Atmosic Technologies Proprietary and Confidential
sheet 3
- Different boost circuits depending on the type of PV cell & efficiency
- Option1: Inductive Boost from Vharv
- Option2: 2-diode Boost from Vstore
- Option3: 2-diode Boost from Vharv
- - Best Efficiency option for all PV cell within Vharv range
- - Cost Optimized option for all PV cell within Vharv range
- - High Efficiency, Lower Cost option for 6-cell PV
- Vstore
- Vstore
- Vstore
- Short
- VHSC
- Harv_out
- VHSC
- Harv_out
- VHSC
- Harv_out
- Open
- Short
- Short
- Passive
  Boost
- Passive
  Boost
- Passive
  Boost
- Short
- Short
- Short
- Short
- Short
- Open
- Short
- Short
- Short
- Short
- Short
- Short
- Boost_IO
- Boost_IO
- Boost_IO
- MOS
  FET
- Boost IO: P8 CanHarv&MustHarv
- Boost IO: P8 Hardware Control
- Boost IO: P8 Hardware Control
- Note:
  Open is no connection, Short is connection
sheet 4
- INTERNAL VDDIO
  VDDIO=VDDIOP=1.8V
- CapsLock LED
- Keyboard connector
- ATM3330e
- Passive Boost
- Option1(default)
- Change C37 to 22uF if needs
  to operate below -20¢XC
- LED for USB Charger
- Fn Lock /Pairing/Reconnecting
- 32KHZ Xtal
- 16MHZ Xtal
- Option2/Option3
- PV Cell connectors
- LED behavior
  Pairing  - Green LED blinking at 250ms interval
  Fn lock - Green LED always on
  Caps lock - Green LED always on
  none USB and pairing completed without Fn - LED diabled
  USB plug-in and start to charge - Red LED always on
  USB plug-in and charge completed - Gren LED always on (LED will not be
  controlled by Fn-lock when this stage)
  Reconnecting - Green LED blinking at 100ms interval
- P0
- P1
- P2
- P3
- P4
- P5
- P6
- P7
- P8
- P9
- P25 (BBOOT)
- LED -G
- LED -R
- P10
- Pairing
- 1 0 1 0
- Flash
- OFF
- P11
- P12
- P13
- P14
- Fn Lock
- 1
- ON
- OFF
- P15
- USB plug-in and charge battery
- P16
- 0
- OFF
- ON
- P17
- USB plug-in and charge complete
- 1
- ON
- OFF
- P18
- P19
- P20
- none USB and pairing completed without Fn
- 0
- OFF
- OFF
- P21
- DM5
- DM6
- DM7
- DM17
- DM21
- DM22
- DM26
- DM27
- DM28
- DM29
- P22
- DM18 reserve for
  Non Harvesting Application
- Option1
- 0
- 1
- 1
- 1
- 1
- 0
- 1
- 1
- 0
- 0
- P23
- Option2
- 1
- 1
- 0
- 0
- 0
- 1
- 0
- 0
- 1
- 1
- Caps Lock
- NA
- ON
- OFF
- P24
- Reconnecting
- 1 0 1 0
- Flash
- OFF
- Benign boot
- P25
- Option3
- 1
- 1
- 0
- 1
- 0
- 1
- 0
- 0
- 1
- 1
- P26
- Note: 1 means 0 ohm, 0 means DNS.
- P27
- P28
- RF Antenna Matching Value need to be modified
- P29
- P30
- RFIO
- 7X7 QFN
- Fine tune result
- USB Plug-In Reset
- FPC TEST CONNECTOR
- TEST POINTS
- USB to LDO Charger
- Hybrid Supercap
- USB CONNECTOR
- USB Plug-In Detect
- UART0_RX
- UART0_TX
- UART0_CTS
- UART0_RTS
- UART1_TX
- VOUT=0.8V x((RA+RB)/RB)
  3.95V, RA=16.9K, RB=4.3K
- ATMOSIC TECHNOLOGIES INC
- Note: When customer design, can change
  the connector to test pin for factory
  testing.
